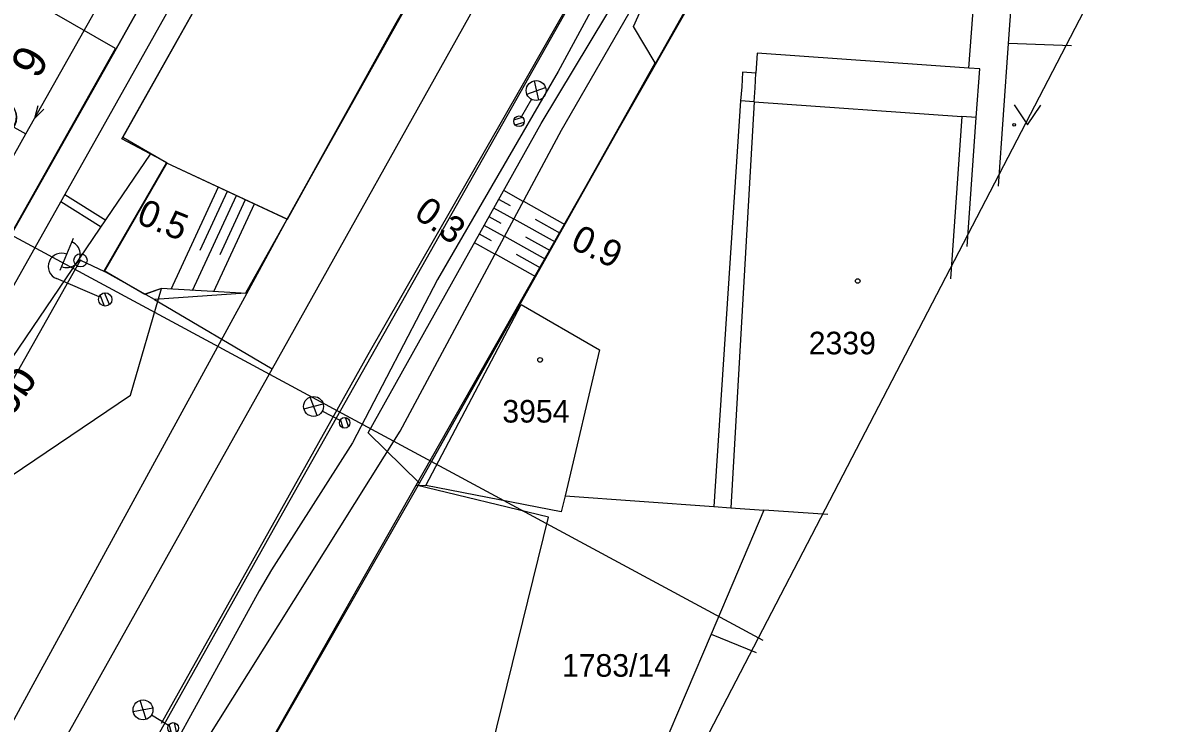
# Model space of a CAD drawing. Extents: x -781083 to -763634, y -1029516 to -1022695.
# Drawn here: x -765174.1 to -765088.2, y -1024274.3 to -1024221.6 of the extents above; entities that cross this region are included whole.
import ezdxf

# ---------------------------------------------------------------- set-up
doc = ezdxf.new("R2010")
doc.units = 0
for name, color, linetype in [('CETIN_nezaměřený', 7, 'Continuous'), ('Hranice parcel', 7, 'Continuous'), ('Parcelní čísla', 7, 'Continuous'), ('PS120111-MOK', 7, 'Continuous'), ('PS_12-01-10_Kabelizace_nove_kabelizace', 7, 'Continuous'), ('SO128401_EOV_trasa', 7, 'Continuous'), ('Vnitřní kresba', 7, 'Continuous'), ('Vrstva 1', 7, 'Continuous'), ('Vrstva 12', 7, 'Continuous'), ('Vrstva 16', 7, 'Continuous'), ('Vrstva 17', 7, 'Continuous'), ('Vrstva 2', 7, 'Continuous'), ('Vrstva 25', 7, 'Continuous'), ('Vrstva 48', 7, 'Continuous'), ('Vrstva 49', 7, 'Continuous'), ('Vrstva 5', 7, 'Continuous'), ('Vrstva 51', 7, 'Continuous'), ('Vrstva 7', 7, 'Continuous'), ('Značky bodu BP', 7, 'Continuous'), ('Značky budov', 7, 'Continuous'), ('Značky kultur', 7, 'Continuous'), ('ČD Telematika_TK', 7, 'Continuous')]:
    doc.layers.add(name, color=color, linetype=linetype)

# ---------------------------------------------------------------- blocks, each defined once
blk = doc.blocks.new('4.02')
at = {"layer": 'Značky budov'}
blk.add_circle((-0.07, 0.01), 1.75, dxfattribs=at)
blk = doc.blocks.new('1.05')
at = {"layer": 'Značky bodu BP'}
for radius in [5, 0.303]:
    blk.add_circle((0, 0), radius, dxfattribs=at)
blk = doc.blocks.new('C669_21')
at = {"layer": 'Vrstva 25'}
for p, q in [((0, 5), (0, 40)), ((7, 40), (33, 40)), ((-4.78, -1.46), (1.44, 4.76)), ((-2.39, -4.37), (4.38, 2.4))]:
    blk.add_line(p, q, dxfattribs=at)
blk.add_circle((0, 0), 5, dxfattribs=at)
blk.add_circle((0, 0), 5, dxfattribs=at)
for centre, start, end in [((10, 40), 0.00012, 180.00012), ((20, 39.88), 179.29754, 0.70269)]:
    blk.add_arc(centre, 10, start, end, dxfattribs=at)
blk = doc.blocks.new('C187_11')
at = {"layer": 'Vrstva 25'}
for p, q in [((-4.94, 32.07), (5, 20.95)), ((-4.79, 20.77), (5.05, 31.98)), ((0, 19), (0, 4)), ((-3.89, -0.8), (0.8, 3.89)), ((-1.21, -3.77), (3.79, 1.23))]:
    blk.add_line(p, q, dxfattribs=at)
for centre, radius in [((-0.03, 26.48), 7.49), ((0, 0), 4), ((0, 0), 4)]:
    blk.add_circle(centre, radius, dxfattribs=at)
blk = doc.blocks.new('C187_12')
at = {"layer": 'Vrstva 25'}
for p, q in [((-4.94, 32.07), (5, 20.95)), ((-4.79, 20.77), (5.05, 31.98)), ((0, 19), (0, 4)), ((-3.88, -0.8), (0.8, 3.89)), ((-1.21, -3.77), (3.79, 1.23))]:
    blk.add_line(p, q, dxfattribs=at)
for centre, radius in [((-0.03, 26.48), 7.49), ((0, 0), 4), ((0, 0), 4)]:
    blk.add_circle(centre, radius, dxfattribs=at)
blk = doc.blocks.new('C187_14')
at = {"layer": 'Vrstva 25'}
for p, q in [((-4.94, 32.07), (5, 20.95)), ((-4.79, 20.78), (5.05, 31.98)), ((0, 19), (0, 4)), ((-3.89, -0.8), (0.8, 3.89)), ((-1.21, -3.77), (3.79, 1.23))]:
    blk.add_line(p, q, dxfattribs=at)
for centre, radius in [((-0.03, 26.49), 7.49), ((0, 0), 4), ((0, 0), 4)]:
    blk.add_circle(centre, radius, dxfattribs=at)
blk = doc.blocks.new('C321')
at = {"layer": 'Vrstva 2'}
blk.add_lwpolyline([(9.66, 2.59), (0, 0), (9.66, -2.59)], dxfattribs=at)
blk = doc.blocks.new('C515_4')
at = {"layer": 'Vrstva 2'}
for p, q in [((-0.02, 35.76), (3.35, 39.13)), ((-0.02, 30.45), (7.16, 37.63)), ((-0.02, 25.15), (10.19, 35.36)), ((-0.03, 19.84), (12.53, 32.4)), ((-0.03, 14.54), (14.1, 28.67)), ((1.1, 10.37), (14.53, 23.79)), ((0, 10.29), (0, 0))]:
    blk.add_line(p, q, dxfattribs=at)
blk.add_lwpolyline([(0, 39.56), (0, 10.29)], dxfattribs=at)
blk.add_circle((0, 24.92), 14.64, dxfattribs=at)
blk.add_arc((0, 24.92), 14.63, 270.01913, 89.97998, dxfattribs=at)

msp = doc.modelspace()

# ---------------------------------------------------------------- linework, layer by layer
msp.add_lwpolyline([(-765336.117, -1024363.479), (-765204.05, -1024432.093), (-764769.725, -1023596.107), (-764901.792, -1023527.494)], close=True)
at = {"layer": 'CETIN_nezaměřený'}
msp.add_lwpolyline([(-765127.3, -1024213.2), (-765133.81, -1024225.23), (-765142.89, -1024240.89), (-765149.3, -1024253.19), (-765155.4, -1024262.74), (-765156.32, -1024264.33), (-765163.03, -1024276.53)], dxfattribs=at)
at = {"layer": 'Hranice parcel'}
for p, q in [((-765094.59, -1024138.97), (-765155.36, -1024247.61)), ((-765099.88, -1024223.1), (-765099.04, -1024210.87)), ((-765100.626, -1024233.85), (-765099.88, -1024223.1)), ((-765095.139, -1024223.288), (-765099.88, -1024223.1)), ((-765164.22, -1024242.38), (-765167.98, -1024240.28)), ((-765164.22, -1024242.38), (-765155.36, -1024247.61)), ((-765174.11, -1024308.46), (-765144.5, -1024256.37)), ((-765144.5, -1024256.37), (-765143.78, -1024256.41)), ((-765133.28, -1024257.17), (-765122.08, -1024257.98))]:
    msp.add_line(p, q, dxfattribs=at)
for points in [[(-765187.73, -1024334.42), (-765188.8, -1024333), (-765188.73, -1024329.7), (-765187.34, -1024321.79), (-765186.15, -1024317.88), (-765184.1, -1024312.59), (-765182.16, -1024308.4), (-765174.96, -1024294.85), (-765154.33, -1024258.05), (-765087.21, -1024139.28), (-765076.299, -1024121.401)], [(-765167.98, -1024240.28), (-765163.25, -1024232.1), (-765166.67, -1024230.28), (-765110.28, -1024130.11), (-765108.75, -1024130.98)], [(-765101.44, -1024140.15), (-765100.4, -1024140.74), (-765129.91, -1024192.98), (-765157.35, -1024241.92), (-765164.22, -1024242.38)], [(-765144.5, -1024256.37), (-765131.19, -1024232.95), (-765113.91, -1024202.71), (-765113.49, -1024201.95)], [(-765102.986, -1024238.392), (-765102.31, -1024228.68), (-765102.05, -1024225.03), (-765102.88, -1024224.97), (-765118.82, -1024223.84), (-765118.91, -1024225.35), (-765119.91, -1024225.28), (-765119.97, -1024226.38), (-765120.07, -1024227.43), (-765122.08, -1024257.98)], [(-765199.67, -1024294.27), (-765200.37, -1024293.59), (-765169.79, -1024239.44), (-765167.98, -1024240.28)], [(-765143.78, -1024256.41), (-765136.58, -1024242.77), (-765130.68, -1024246.18), (-765133.28, -1024257.17)], [(-765155.36, -1024247.61), (-765159.55, -1024255.1), (-765180.19, -1024291.92), (-765185.57, -1024302.05)], [(-765148.25, -1024314.45), (-765143.42, -1024294.84), (-765141.28, -1024286.17), (-765138.81, -1024276.14), (-765134.54, -1024258.78), (-765144.5, -1024256.37)], [(-765133.28, -1024257.17), (-765133.57, -1024258.38), (-765143.78, -1024256.41)], [(-765118.31, -1024258.25), (-765122.29, -1024267.6), (-765126.05, -1024276.43), (-765132.4, -1024291.35), (-765138.97, -1024303.69), (-765141.77, -1024306.94), (-765144.65, -1024310.28), (-765145.45, -1024311.2), (-765148.25, -1024314.45)], [(-765122.08, -1024257.98), (-765120.81, -1024258.07), (-765118.31, -1024258.25)], [(-765113.482, -1024258.594), (-765118.31, -1024258.25)]]:
    msp.add_lwpolyline(points, dxfattribs=at)
at = {"layer": 'PS120111-MOK'}
msp.add_lwpolyline([(-765225.805, -1024328.474), (-765227.041, -1024327.403), (-765189.607, -1024263.284), (-765167.089, -1024223.521), (-765111.836, -1024124.939), (-765108.851, -1024119.501), (-765085.73, -1024077.899), (-765081.023, -1024080.523), (-765060.822, -1024044.042), (-765057.835, -1024038.647), (-765021.888, -1023965.037), (-765009.529, -1023945.01), (-764990.029, -1023909.994), (-764973.93, -1023884.565), (-764957.796, -1023847.878), (-764953.349, -1023837.037), (-764952.504, -1023834.976), (-764951.393, -1023835.06)], dxfattribs=at)
at = {"layer": 'PS_12-01-10_Kabelizace_nove_kabelizace'}
msp.add_lwpolyline([(-765057.835, -1024038.647), (-765081.023, -1024080.523), (-765085.73, -1024077.899), (-765108.851, -1024119.501), (-765111.836, -1024124.939), (-765167.089, -1024223.521), (-765189.607, -1024263.284)], dxfattribs=at)
at = {"layer": 'SO128401_EOV_trasa'}
msp.add_lwpolyline([(-765111.624, -1024019.292), (-765109.87, -1024016.203), (-765060.824, -1024044.045), (-765060.824, -1024044.045), (-765081.023, -1024080.523), (-765081.023, -1024080.523), (-765085.73, -1024077.899), (-765108.851, -1024119.501), (-765111.836, -1024124.939), (-765167.089, -1024223.521), (-765176.711, -1024240.445), (-765189.607, -1024263.284), (-765189.607, -1024263.284), (-765225.916, -1024325.475), (-765224.46, -1024326.168)], dxfattribs=at)
at = {"layer": 'Vnitřní kresba'}
for p, q in [((-765102.88, -1024224.97), (-765101.34, -1024204.48)), ((-765118.97, -1024226.44), (-765118.91, -1024225.35)), ((-765119.03, -1024227.5), (-765118.97, -1024226.44)), ((-765119.03, -1024227.5), (-765120.07, -1024227.43)), ((-765119.03, -1024227.5), (-765120.81, -1024258.07)), ((-765119.03, -1024227.5), (-765103.4, -1024228.6)), ((-765103.4, -1024228.6), (-765104.256, -1024240.836)), ((-765102.31, -1024228.68), (-765103.4, -1024228.6)), ((-765122.29, -1024267.6), (-765118.882, -1024268.988))]:
    msp.add_line(p, q, dxfattribs=at)
at = {"layer": 'Vrstva 1'}
for points in [[(-765173.904, -1024229.916), (-765173.254, -1024228.763), (-765165.873, -1024215.668), (-765157.715, -1024201.193), (-765150.799, -1024188.931), (-765144.602, -1024177.925), (-765137.347, -1024165.014), (-765128.994, -1024150.127), (-765120.916, -1024135.756), (-765114.604, -1024124.554), (-765112.054, -1024120.015), (-765110.861, -1024117.895), (-765104.54, -1024106.641), (-765100.051, -1024098.661), (-765087.977, -1024077.275), (-765086.765, -1024075.13), (-765078.232, -1024059.989), (-765070.151, -1024045.656), (-765065.795, -1024037.884), (-765064.623, -1024035.796), (-765055.87, -1024020.2), (-765054.667, -1024018.056), (-765047.51, -1024005.326), (-765040.997, -1023993.749)], [(-765196.085, -1024278.806), (-765194.209, -1024275.468), (-765190.323, -1024268.633), (-765181.566, -1024253.231), (-765176.626, -1024244.51), (-765168.111, -1024229.414), (-765158.27, -1024211.855), (-765152.182, -1024200.956), (-765148.92, -1024195.244), (-765140.746, -1024180.761), (-765133.358, -1024167.67), (-765132.595, -1024166.323)], [(-765227.172, -1024323.332), (-765226.383, -1024321.987), (-765218.823, -1024308.994), (-765210.425, -1024294.562), (-765204.319, -1024283.867), (-765196.481, -1024270.015), (-765194.577, -1024266.628), (-765187.356, -1024253.776), (-765179.867, -1024240.503), (-765173.904, -1024229.916)], [(-765179.467, -1024253.46), (-765167.817, -1024236.316), (-765164.509, -1024231.448)]]:
    msp.add_lwpolyline(points, dxfattribs=at)
at = {"layer": 'Vrstva 12'}
for points in [[(-765163.302, -1024232.095), (-765166.602, -1024230.181), (-765141.627, -1024185.724)], [(-765163.301, -1024232.096), (-765166.6, -1024230.183), (-765141.624, -1024185.717)], [(-765145.998, -1024221.55), (-765154.211, -1024236.34)], [(-765154.198, -1024236.334), (-765146.005, -1024221.554)], [(-765166.6, -1024230.183), (-765166.602, -1024230.181)], [(-765168.012, -1024240.226), (-765163.302, -1024232.095)], [(-765163.696, -1024241.562), (-765164.939, -1024242.009), (-765168.01, -1024240.228), (-765163.301, -1024232.096)], [(-765163.301, -1024232.096), (-765163.302, -1024232.095)], [(-765163.302, -1024232.095), (-765154.211, -1024236.34)], [(-765163.301, -1024232.096), (-765154.198, -1024236.334)], [(-765154.198, -1024236.334), (-765154.211, -1024236.34)], [(-765157.256, -1024241.948), (-765163.696, -1024241.562), (-765164.932, -1024242.002), (-765168.012, -1024240.226)], [(-765168.01, -1024240.228), (-765168.012, -1024240.226)], [(-765164.939, -1024242.009), (-765164.932, -1024242.002)]]:
    msp.add_lwpolyline(points, dxfattribs=at)
at = {"layer": 'Vrstva 16'}
msp.add_lwpolyline([(-765183.248, -1024261.22), (-765166.012, -1024249.586), (-765163.696, -1024241.562)], dxfattribs=at)
at = {"layer": 'Vrstva 17'}
for points in [[(-765144.238, -1024256.217), (-765125.325, -1024222.555), (-765118.034, -1024209.605)], [(-765174.12, -1024308.406), (-765144.238, -1024256.217)]]:
    msp.add_lwpolyline(points, dxfattribs=at)
at = {"layer": 'Vrstva 2'}
msp.add_lwpolyline([(-765173.904, -1024229.916), (-765173.254, -1024228.763), (-765165.873, -1024215.668), (-765157.715, -1024201.193)], dxfattribs=at)
at = {"layer": 'Vrstva 48'}
for p, q in [((-765162.969, -1024241.606), (-765159.39, -1024233.917)), ((-765160.783, -1024238.686), (-765158.71, -1024234.233)), ((-765136.442, -1024235.015), (-765137.909, -1024234.195)), ((-765161.36, -1024241.702), (-765158.03, -1024234.55)), ((-765159.273, -1024238.997), (-765157.35, -1024234.866)), ((-765137.388, -1024235.345), (-765138.275, -1024234.85)), ((-765136.428, -1024234.988), (-765133.299, -1024236.747)), ((-765159.75, -1024241.798), (-765156.67, -1024235.183)), ((-765137.152, -1024236.336), (-765138.641, -1024235.504)), ((-765137.861, -1024237.658), (-765139.373, -1024236.813)), ((-765138.107, -1024236.662), (-765139.007, -1024236.159)), ((-765137.137, -1024236.309), (-765134.033, -1024238.053)), ((-765135.536, -1024236.349), (-765133.666, -1024237.4)), ((-765138.825, -1024237.979), (-765139.739, -1024237.468)), ((-765137.846, -1024237.629), (-765134.767, -1024239.36)), ((-765136.255, -1024237.664), (-765134.4, -1024238.706)), ((-765138.571, -1024238.98), (-765140.105, -1024238.123)), ((-765138.555, -1024238.95), (-765135.501, -1024240.666)), ((-765136.974, -1024238.979), (-765135.134, -1024240.013))]:
    msp.add_line(p, q, dxfattribs=at)
at = {"layer": 'Vrstva 49'}
for points in [[(-765174.12, -1024308.406), (-765144.238, -1024256.217), (-765126.49, -1024224.567), (-765128.139, -1024221.83), (-765124.809, -1024214.48)], [(-765160.543, -1024275.992), (-765145.719, -1024252.299), (-765133.555, -1024229.635), (-765124.809, -1024214.48)], [(-765148.11, -1024252.438), (-765135.086, -1024229.147), (-765126.455, -1024214.776), (-765124.809, -1024214.48)], [(-765173.205, -1024271.109), (-765157.256, -1024241.948)], [(-765144.238, -1024256.217), (-765148.11, -1024252.438)]]:
    msp.add_lwpolyline(points, dxfattribs=at)
at = {"layer": 'Vrstva 5'}
msp.add_line((-765187.775, -1024230.633), (-765118.399, -1024268.058), dxfattribs=at)
at = {"layer": 'Vrstva 51'}
for points in [[(-765157.256, -1024241.948), (-765154.211, -1024236.34), (-765145.998, -1024221.55), (-765140.254, -1024211.571), (-765129.912, -1024193.175)], [(-765163.691, -1024274.3), (-765148.115, -1024246.532), (-765136.594, -1024226.436), (-765125.912, -1024207.701), (-765123.226, -1024207.025), (-765118.034, -1024209.605)], [(-765182.878, -1024288.822), (-765173.205, -1024271.109)]]:
    msp.add_lwpolyline(points, dxfattribs=at)
at = {"layer": 'Vrstva 7'}
for p, q in [((-765171.271, -1024235.016), (-765168.22, -1024236.909)), ((-765170.975, -1024234.492), (-765167.882, -1024236.412))]:
    msp.add_line(p, q, dxfattribs=at)
at = {"layer": 'Značky kultur'}
msp.add_lwpolyline([(-765099.45, -1024227.739), (-765098.45, -1024229.24), (-765097.456, -1024227.748)], dxfattribs=at)
msp.add_circle((-765099.45, -1024229.239), 0.1, dxfattribs=at)
at = {"layer": 'ČD Telematika_TK'}
msp.add_lwpolyline([(-765257.028, -1024404.569), (-765256.037, -1024398.213), (-765249.421, -1024374.188), (-765226.425, -1024328.292), (-765185.224, -1024255.545), (-765167.149, -1024223.486), (-765171.928, -1024220.746), (-765141.483, -1024166.52), (-765136.718, -1024169.454), (-765086.954, -1024080.425), (-765063.726, -1024094.284), (-765054.277, -1024080.444), (-765052.94, -1024078.307), (-765049.809, -1024079.983), (-765033.351, -1024048.633), (-765033.134, -1024014.623), (-765034.915, -1024000.619), (-765019.65, -1023968.646), (-765007.996, -1023946.352)], dxfattribs=at)

# ---------------------------------------------------------------- block references
at = {"layer": 'Vrstva 2'}
for name, p, xscale, yscale, rotation in [('C515_4', (-765173.904, -1024229.916), 0.1, 0.10000000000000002, 60.610138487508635), ('C321', (-765173.254, -1024228.763), 0.09999999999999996, 0.09999999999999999, 60.59352783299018)]:
    msp.add_blockref(name, p, dxfattribs=dict(at, xscale=xscale, yscale=yscale, rotation=rotation))
at = {"layer": 'Vrstva 25'}
for name, p, xscale, yscale, rotation in [('C187_12', (-765136.755, -1024228.969), 0.1, 0.09999999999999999, -29.27399542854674), ('C669_21', (-765167.922, -1024242.387), 0.09999999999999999, 0.09999999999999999, 66.96798471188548), ('C187_14', (-765149.887, -1024251.676), 0.10000000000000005, 0.10000000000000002, 62.223034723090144), ('C187_11', (-765162.806, -1024274.658), 0.09999999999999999, 0.09999999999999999, 59.0430811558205)]:
    msp.add_blockref(name, p, dxfattribs=dict(at, xscale=xscale, yscale=yscale, rotation=rotation))
at = {"layer": 'Značky bodu BP', "xscale": 0.1, "yscale": 0.10000000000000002}
msp.add_blockref('1.05', (-765169.79, -1024239.44), dxfattribs=at)
at = {"layer": 'Značky budov', "xscale": 0.1, "yscale": 0.10000000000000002}
for p in [(-765111.23, -1024241), (-765135.16, -1024246.94)]:
    msp.add_blockref('4.02', p, dxfattribs=at)

# ---------------------------------------------------------------- texts
at = {"layer": 'Parcelní čísla'}
for s, p in [('2339', (-765114.93, -1024246.52)), ('3954', (-765138.01, -1024251.66)), ('1783/14', (-765133.52, -1024270.8))]:
    msp.add_text(s, height=1.7, dxfattribs=at).set_placement(p)
at = {"layer": 'Vrstva 1'}
msp.add_text('6b', height=2.5, rotation=55.8024, dxfattribs=at).set_placement((-765175.056, -1024251.417))
at = {"layer": 'Vrstva 2'}
msp.add_text('9', height=2.5, rotation=60.61014, dxfattribs=at).set_placement((-765172.987, -1024225.879))
at = {"layer": 'Vrstva 48'}
for s, rotation, p in [('0.5', 337.87517, (-765165.658, -1024236.607)), ('0.3', 323.8994, (-765144.759, -1024236.128)), ('0.9', 334.4369, (-765132.969, -1024238.49))]:
    msp.add_text(s, height=2, rotation=rotation, dxfattribs=at).set_placement(p)

doc.saveas('drawing.dxf')
